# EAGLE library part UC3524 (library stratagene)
SWITCHMODE Pulse Width Modulation Control Circuit NCV494B http://onsemi.com tl494-d.pdf
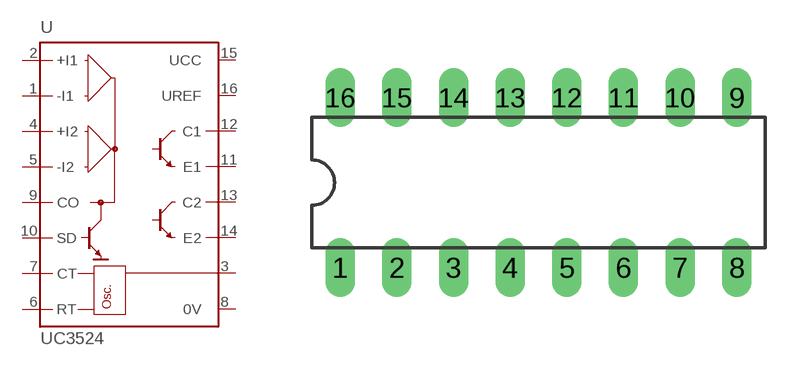
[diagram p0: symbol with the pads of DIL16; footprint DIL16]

Designator prefix U

## UC3524CN, UC3524IN  [DIL16]
1  -I1  in
2  +I1  in
3  OSCOUT  out
4  +I2  in
5  -I2  in
6  RT  pas
7  CT  pas
8  0V  pwr
9  CO  pas
10  SD  pas
11  E1  pas
12  C1  pas
13  C2  pas
14  E2  pas
15  UCC  pwr
16  UREF  in

## Footprint DIL16 (pad centres in mm)
Dual In Line Package
drill 0.813 long: 1 -8.89,-3.81; 2 -6.35,-3.81; 3 -3.81,-3.81; 4 -1.27,-3.81; 5 1.27,-3.81; 6 3.81,-3.81; 7 6.35,-3.81; 8 8.89,-3.81; 9 8.89,3.81; 10 6.35,3.81; 11 3.81,3.81; 12 1.27,3.81; 13 -1.27,3.81; 14 -3.81,3.81; 15 -6.35,3.81; 16 -8.89,3.81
